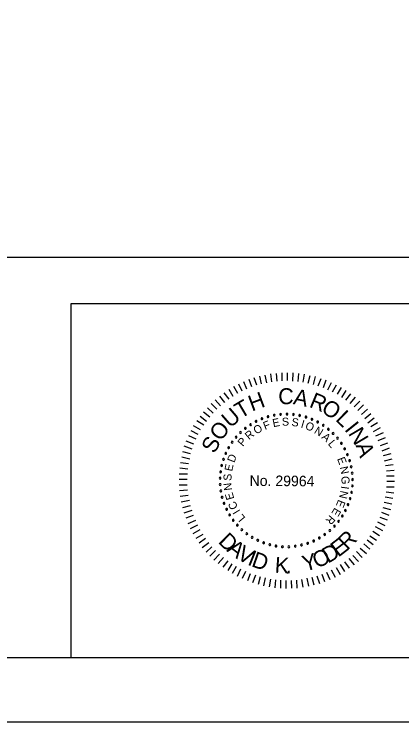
# Model space of a CAD drawing. Extents: x -133.1 to -97, y -1.7 to 20.3.
# Drawn here: x -110.95 to -107.94, y -1.69 to 3.81 of the extents above; entities that cross this region are included whole.
import ezdxf

# ---------------------------------------------------------------- set-up
doc = ezdxf.new("R2010")
doc.units = 0
for name, color, linetype in [('BR_AUTO DIMENSION', 7, 'Continuous'), ('BR_BORDER LINES', 7, 'Continuous'), ('BR_TEXT', 7, 'Continuous'), ('Level 31', 7, 'Continuous')]:
    doc.layers.add(name, color=color, linetype=linetype)

msp = doc.modelspace()

# ---------------------------------------------------------------- linework, layer by layer
at = {"layer": 'BR_AUTO DIMENSION'}
msp.add_lwpolyline([(-124.7207, 1.9196), (-106.7207, 1.9196), (-106.7207, 13.8928), (-124.7207, 13.8928)], close=True, dxfattribs=at)
at = {"layer": 'BR_BORDER LINES'}
for p, q in [((-110.5071, 1.5591), (-105.1419, 1.5591)), ((-110.5071, -1.191), (-110.5071, 1.5591)), ((-131.3076, -1.191), (-97.6416, -1.191))]:
    msp.add_line(p, q, dxfattribs=at)
at = {"layer": 'BR_TEXT'}
for p, q in [((-109.0262, 0.9348), (-109.0394, 0.9958)), ((-108.9849, 0.9447), (-108.999, 1.0041)), ((-108.9454, 0.9521), (-108.9543, 1.0131)), ((-108.9059, 0.9561), (-108.9097, 1.017)), ((-108.8664, 0.9584), (-108.8658, 1.0227)), ((-108.8243, 0.9606), (-108.8238, 1.0224)), ((-108.7823, 0.9577), (-108.78, 1.022)), ((-108.742, 0.9548), (-108.7372, 1.0156)), ((-108.7034, 0.9501), (-108.6926, 1.011)), ((-108.6631, 0.9421), (-108.6489, 1.0012)), ((-108.622, 0.9314), (-108.606, 0.9922)), ((-109.1406, 0.8954), (-109.1642, 0.9514)), ((-109.1019, 0.9122), (-109.1229, 0.9708)), ((-109.0623, 0.9248), (-109.0842, 0.9824)), ((-108.5852, 0.9208), (-108.5633, 0.9781)), ((-108.5458, 0.9076), (-108.5239, 0.9658)), ((-108.5099, 0.8902), (-108.482, 0.9457)), ((-109.2475, 0.8371), (-109.278, 0.8914)), ((-109.2122, 0.8608), (-109.2426, 0.9151)), ((-109.1777, 0.8785), (-109.2039, 0.9345)), ((-108.474, 0.8727), (-108.4427, 0.9282)), ((-108.4364, 0.8544), (-108.4042, 0.9082)), ((-108.4031, 0.8301), (-108.3692, 0.8839)), ((-109.3123, 0.7904), (-109.3522, 0.8405)), ((-109.2786, 0.8159), (-109.3177, 0.8668)), ((-108.3699, 0.8083), (-108.3334, 0.8587)), ((-108.3375, 0.7824), (-108.2968, 0.8318)), ((-109.3745, 0.7386), (-109.4188, 0.7827)), ((-109.3451, 0.7658), (-109.3868, 0.8107)), ((-108.3059, 0.7572), (-108.2627, 0.8014)), ((-108.2779, 0.7295), (-108.2346, 0.7729)), ((-109.4291, 0.6763), (-109.4786, 0.7154)), ((-109.4039, 0.7079), (-109.4474, 0.7503)), ((-108.2498, 0.6984), (-108.2022, 0.74)), ((-109.4551, 0.6431), (-109.5046, 0.683)), ((-108.2226, 0.6664), (-108.1759, 0.7046)), ((-108.1988, 0.6327), (-108.1496, 0.6718)), ((-109.5012, 0.5774), (-109.5549, 0.6096)), ((-109.4768, 0.6141), (-109.5306, 0.6472)), ((-108.1768, 0.6034), (-108.1242, 0.6355)), ((-109.5186, 0.5432), (-109.575, 0.5711)), ((-108.1548, 0.5663), (-108.1013, 0.5976)), ((-108.137, 0.5318), (-108.0793, 0.5588)), ((-109.5361, 0.5065), (-109.5933, 0.5318)), ((-108.1193, 0.4948), (-108.0624, 0.5192)), ((-109.5659, 0.4278), (-109.6275, 0.4506)), ((-109.5536, 0.468), (-109.6117, 0.4899)), ((-108.1025, 0.456), (-108.0456, 0.477)), ((-109.5782, 0.3918), (-109.639, 0.4069)), ((-108.0891, 0.4156), (-108.0314, 0.4374)), ((-108.079, 0.3794), (-108.0189, 0.3935)), ((-109.5854, 0.3498), (-109.6479, 0.3658)), ((-108.0708, 0.3373), (-108.0106, 0.3522)), ((-109.6006, 0.2727), (-109.6624, 0.2801)), ((-109.596, 0.3138), (-109.6569, 0.3221)), ((-108.0625, 0.3012), (-108.0033, 0.3084)), ((-109.6035, 0.2333), (-109.6679, 0.2338)), ((-108.056, 0.26), (-107.995, 0.2663)), ((-108.0546, 0.2205), (-107.9945, 0.22)), ((-109.6056, 0.1921), (-109.6682, 0.1926)), ((-108.0524, 0.1793), (-107.9915, 0.1788)), ((-109.6042, 0.1492), (-109.6686, 0.148)), ((-109.602, 0.1105), (-109.6638, 0.1033)), ((-108.0553, 0.1364), (-107.9952, 0.1342)), ((-109.598, 0.0693), (-109.659, 0.0604)), ((-108.0645, 0.0566), (-108.0054, 0.0467)), ((-108.0574, 0.0978), (-107.9965, 0.0896)), ((-109.5881, 0.0297), (-109.6508, 0.0165)), ((-108.0735, 0.0172), (-108.0135, 0.003)), ((-109.5815, -0.0124), (-109.6426, -0.0265)), ((-109.5698, -0.0493), (-109.6318, -0.0703)), ((-108.0824, -0.0248), (-108.0224, -0.0398)), ((-109.5582, -0.0881), (-109.6167, -0.1091)), ((-108.107, -0.1001), (-108.0506, -0.122)), ((-108.093, -0.0615), (-108.0357, -0.0835)), ((-109.5413, -0.1251), (-109.599, -0.1521)), ((-109.5244, -0.1613), (-109.5813, -0.1909)), ((-108.1245, -0.1368), (-108.0681, -0.1647)), ((-109.5076, -0.1984), (-109.5619, -0.2297)), ((-108.1612, -0.2095), (-108.1082, -0.2417)), ((-108.1428, -0.1727), (-108.0856, -0.2032)), ((-109.4838, -0.2355), (-109.5382, -0.2668)), ((-109.4626, -0.2648), (-109.5127, -0.3013)), ((-108.1838, -0.2462), (-108.1317, -0.2784)), ((-109.4372, -0.2985), (-109.4873, -0.3376)), ((-108.2306, -0.3084), (-108.1846, -0.3483)), ((-108.2063, -0.2752), (-108.1577, -0.3125)), ((-109.4125, -0.3321), (-109.4567, -0.373)), ((-109.3836, -0.3582), (-109.4286, -0.4032)), ((-108.2869, -0.3672), (-108.2444, -0.413)), ((-108.2583, -0.3417), (-108.2115, -0.3833)), ((-109.3547, -0.3884), (-109.3971, -0.4344)), ((-109.3222, -0.4144), (-109.363, -0.4613)), ((-108.3474, -0.4225), (-108.3075, -0.47)), ((-108.3155, -0.397), (-108.273, -0.4437)), ((-109.289, -0.4404), (-109.3289, -0.4882)), ((-109.2583, -0.4622), (-109.2896, -0.5142)), ((-109.2233, -0.4847), (-109.2546, -0.5386)), ((-108.4475, -0.4911), (-108.4162, -0.5455)), ((-108.4139, -0.4691), (-108.3808, -0.5217)), ((-108.3802, -0.448), (-108.3446, -0.4963)), ((-109.1891, -0.5048), (-109.2162, -0.5603)), ((-109.1523, -0.5222), (-109.1769, -0.5778)), ((-109.1139, -0.5397), (-109.1358, -0.5962)), ((-108.5578, -0.5443), (-108.5368, -0.6011)), ((-108.5216, -0.5274), (-108.4947, -0.5835)), ((-108.4855, -0.5106), (-108.455, -0.5666)), ((-109.0745, -0.552), (-109.0973, -0.6102)), ((-109.0386, -0.5644), (-109.0528, -0.6235)), ((-108.9974, -0.5716), (-109.0126, -0.6333)), ((-108.9581, -0.5831), (-108.968, -0.6413)), ((-108.9186, -0.5877), (-108.9234, -0.6494)), ((-108.8792, -0.5906), (-108.8797, -0.6524)), ((-108.8372, -0.5935), (-108.8377, -0.6544)), ((-108.7951, -0.5913), (-108.7939, -0.6531)), ((-108.7547, -0.589), (-108.7509, -0.6509)), ((-108.7161, -0.5851), (-108.7062, -0.6435)), ((-108.6756, -0.5742), (-108.6624, -0.6361)), ((-108.6344, -0.5677), (-108.6194, -0.627)), ((-108.5974, -0.556), (-108.5764, -0.6145))]:
    msp.add_line(p, q, dxfattribs=at)
for centre, start, end in [((-109.0235, 0.6646), 21.6807, 201.6807), ((-109.0235, 0.6646), 201.6807, 21.6807), ((-108.9763, 0.6806), 16.1422, 196.1422), ((-108.9763, 0.6806), 196.1422, 16.1422), ((-108.9278, 0.692), 10.6038, 190.6038), ((-108.9278, 0.692), 190.6038, 10.6038), ((-108.8784, 0.6987), 5.0653, 185.0653), ((-108.8784, 0.6987), 185.0653, 5.0653), ((-108.8286, 0.7006), 359.5268, 179.5268), ((-108.8286, 0.7006), 179.5268, 359.5268), ((-108.7789, 0.6977), 173.9884, 353.9884), ((-108.7789, 0.6977), 353.9884, 173.9884), ((-108.7296, 0.69), 168.4499, 348.4499), ((-108.7296, 0.69), 348.4499, 168.4499), ((-108.6814, 0.6776), 162.9114, 342.9114), ((-108.6814, 0.6776), 342.9114, 162.9114), ((-108.6345, 0.6606), 157.373, 337.373), ((-108.6345, 0.6606), 337.373, 157.373), ((-109.1121, 0.6192), 32.7576, 212.7576), ((-109.1121, 0.6192), 212.7576, 32.7576), ((-109.0689, 0.644), 27.2191, 207.2191), ((-109.0689, 0.644), 207.2191, 27.2191), ((-108.5896, 0.6391), 151.8345, 331.8345), ((-108.5896, 0.6391), 331.8345, 151.8345), ((-108.5469, 0.6134), 146.2961, 326.2961), ((-108.5469, 0.6134), 326.2961, 146.2961), ((-109.1903, 0.5577), 43.8345, 223.8345), ((-109.1903, 0.5577), 223.8345, 43.8345), ((-109.1527, 0.5903), 38.2961, 218.2961), ((-109.1527, 0.5903), 218.2961, 38.2961), ((-108.5069, 0.5837), 140.7576, 320.7576), ((-108.5069, 0.5837), 320.7576, 140.7576), ((-108.4699, 0.5503), 135.2191, 315.2191), ((-108.4699, 0.5503), 315.2191, 135.2191), ((-109.2246, 0.5215), 49.373, 229.373), ((-109.2246, 0.5215), 229.373, 49.373), ((-108.4363, 0.5134), 129.6807, 309.6807), ((-108.4363, 0.5134), 309.6807, 129.6807), ((-109.282, 0.4402), 60.4499, 240.4499), ((-109.282, 0.4402), 240.4499, 60.4499), ((-109.2553, 0.4822), 54.9114, 234.9114), ((-109.2553, 0.4822), 234.9114, 54.9114), ((-108.4065, 0.4735), 124.1422, 304.1422), ((-108.4065, 0.4735), 304.1422, 124.1422), ((-109.3045, 0.3957), 65.9884, 245.9884), ((-109.3045, 0.3957), 245.9884, 65.9884), ((-108.3806, 0.4309), 118.6038, 298.6038), ((-108.3806, 0.4309), 298.6038, 118.6038), ((-108.359, 0.3861), 113.0653, 293.0653), ((-108.359, 0.3861), 293.0653, 113.0653), ((-109.3227, 0.3493), 71.5268, 251.5268), ((-109.3227, 0.3493), 251.5268, 71.5268), ((-108.3418, 0.3393), 107.5268, 287.5268), ((-108.3418, 0.3393), 287.5268, 107.5268), ((-109.3363, 0.3014), 77.0653, 257.0653), ((-109.3363, 0.3014), 257.0653, 77.0653), ((-108.3292, 0.2911), 101.9884, 281.9884), ((-108.3292, 0.2911), 281.9884, 101.9884), ((-109.3452, 0.2524), 82.6038, 262.6038), ((-109.3452, 0.2524), 262.6038, 82.6038), ((-108.3213, 0.2419), 96.4499, 276.4499), ((-108.3213, 0.2419), 276.4499, 96.4499), ((-109.3493, 0.2027), 88.1422, 268.1422), ((-109.3493, 0.2027), 268.1422, 88.1422), ((-108.3182, 0.1921), 90.9114, 270.9114), ((-108.3182, 0.1921), 270.9114, 90.9114), ((-109.3486, 0.1529), 93.6807, 273.6807), ((-109.3431, 0.1033), 99.2191, 279.2191), ((-109.3486, 0.1529), 273.6807, 93.6807), ((-109.3431, 0.1033), 279.2191, 99.2191), ((-108.3199, 0.1423), 85.373, 265.373), ((-108.3199, 0.1423), 265.373, 85.373), ((-109.3328, 0.0546), 104.7576, 284.7576), ((-109.3328, 0.0546), 284.7576, 104.7576), ((-108.3265, 0.0929), 79.8345, 259.8345), ((-108.3265, 0.0929), 259.8345, 79.8345), ((-109.3179, 0.007), 110.2961, 290.2961), ((-109.3179, 0.007), 290.2961, 110.2961), ((-108.3536, -0.0028), 68.7576, 248.7576), ((-108.3536, -0.0028), 248.7576, 68.7576), ((-108.3377, 0.0444), 74.2961, 254.2961), ((-108.3377, 0.0444), 254.2961, 74.2961), ((-109.2985, -0.0389), 115.8345, 295.8345), ((-109.2985, -0.0389), 295.8345, 115.8345), ((-108.374, -0.0483), 63.2191, 243.2191), ((-108.374, -0.0483), 243.2191, 63.2191), ((-109.2747, -0.0826), 121.373, 301.373), ((-109.2747, -0.0826), 301.373, 121.373), ((-108.3986, -0.0916), 57.6807, 237.6807), ((-108.3986, -0.0916), 237.6807, 57.6807), ((-109.2468, -0.1239), 126.9114, 306.9114), ((-109.2468, -0.1239), 306.9114, 126.9114), ((-109.2151, -0.1624), 132.4499, 312.4499), ((-109.2151, -0.1624), 312.4499, 132.4499), ((-108.4599, -0.1701), 46.6038, 226.6038), ((-108.4273, -0.1323), 52.1422, 232.1422), ((-108.4273, -0.1323), 232.1422, 52.1422), ((-109.1798, -0.1975), 137.9884, 317.9884), ((-109.1798, -0.1975), 317.9884, 137.9884), ((-108.4959, -0.2045), 41.0653, 221.0653), ((-108.4959, -0.2045), 221.0653, 41.0653), ((-108.4599, -0.1701), 226.6038, 46.6038), ((-109.1413, -0.2291), 143.5268, 323.5268), ((-109.1413, -0.2291), 323.5268, 143.5268), ((-109.0999, -0.2569), 149.0653, 329.0653), ((-109.0999, -0.2569), 329.0653, 149.0653), ((-109.056, -0.2805), 334.6038, 154.6038), ((-108.577, -0.2622), 29.9884, 209.9884), ((-108.577, -0.2622), 209.9884, 29.9884), ((-108.5351, -0.2353), 35.5268, 215.5268), ((-108.5351, -0.2353), 215.5268, 35.5268), ((-109.056, -0.2805), 154.6038, 334.6038), ((-109.01, -0.2997), 160.1422, 340.1422), ((-109.01, -0.2997), 340.1422, 160.1422), ((-108.9624, -0.3145), 165.6807, 345.6807), ((-108.9624, -0.3145), 345.6807, 165.6807), ((-108.9136, -0.3245), 171.2191, 351.2191), ((-108.9136, -0.3245), 351.2191, 171.2191), ((-108.8641, -0.3299), 356.7576, 176.7576), ((-108.8641, -0.3299), 176.7576, 356.7576), ((-108.8142, -0.3304), 2.2961, 182.2961), ((-108.7646, -0.3261), 7.8345, 187.8345), ((-108.7646, -0.3261), 187.8345, 7.8345), ((-108.7156, -0.317), 13.373, 193.373), ((-108.7156, -0.317), 193.373, 13.373), ((-108.6677, -0.3032), 18.9114, 198.9114), ((-108.6677, -0.3032), 198.9114, 18.9114), ((-108.6214, -0.2849), 24.4499, 204.4499), ((-108.6214, -0.2849), 204.4499, 24.4499), ((-108.8142, -0.3304), 182.2961, 2.2961)]:
    msp.add_arc(centre, 0.00701, start, end, dxfattribs=at)
at = {"layer": 'Level 31'}
msp.add_lwpolyline([(-133.1409, -1.691), (-97.141, -1.691), (-97.141, 20.309), (-133.1409, 20.309)], close=True, dxfattribs=at)

# ---------------------------------------------------------------- texts
at = {"layer": 'BR_TEXT'}
for s, height, rotation, p in [('C', 0.1241, 359.5482, (-108.8971, 0.7782)), ('A', 0.1241, 348.1981, (-108.7857, 0.779)), ('H', 0.1241, 20.3637, (-109.1015, 0.7199)), ('R', 0.1241, 337.4344, (-108.6624, 0.7591)), ('T', 0.1241, 30.4992, (-109.1894, 0.6624)), ('O', 0.1239, 326.5869, (-108.5702, 0.7224)), ('U', 0.1241, 40.8022, (-109.2706, 0.5876)), ('L', 0.1241, 315.9488, (-108.4576, 0.6546)), ('E', 0.0622, 11.4103, (-108.9351, 0.5987)), ('S', 0.0622, 2.208, (-108.8672, 0.6097)), ('S', 0.0622, 352.6608, (-108.796, 0.6095)), ('O', 0.1241, 52.0267, (-109.3451, 0.4837)), ('O', 0.0622, 30.8477, (-109.0676, 0.541)), ('F', 0.0622, 20.6127, (-109.0002, 0.577)), ('I', 0.0622, 343.1136, (-108.7257, 0.5975)), ('O', 0.0622, 338.4392, (-108.6923, 0.5873)), ('N', 0.0622, 328.2042, (-108.6227, 0.5559)), ('I', 0.1241, 308.6613, (-108.3862, 0.5803)), ('R', 0.0622, 40.3949, (-109.1237, 0.4971)), ('N', 0.1241, 300.7037, (-108.3556, 0.5509)), ('S', 0.1239, 63.2511, (-109.3905, 0.3881)), ('P', 0.0622, 49.9421, (-109.1718, 0.4445)), ('A', 0.0622, 318.657, (-108.5637, 0.5159)), ('L', 0.0622, 309.4546, (-108.5139, 0.4686)), ('A', 0.1241, 289.4792, (-108.2964, 0.4579)), ('D', 0.0622, 69.0364, (-109.2388, 0.3192)), ('E', 0.0622, 291.049, (-108.44, 0.3533)), ('E', 0.0622, 78.2388, (-109.2553, 0.2526)), ('N', 0.0622, 281.8466, (-108.4179, 0.2882)), ('S', 0.0622, 87.786, (-109.2611, 0.1815)), ('No. 29964', 0.08175, 359.5268, (-109.1199, 0.1431)), ('G', 0.0622, 272.2995, (-108.4061, 0.2179)), ('N', 0.0622, 97.3332, (-109.2549, 0.1105)), ('I', 0.0622, 262.4084, (-108.4065, 0.1441)), ('E', 0.0622, 106.5355, (-109.2379, 0.044)), ('N', 0.0622, 257.7339, (-108.411, 0.1095)), ('C', 0.0622, 116.4266, (-109.208, -0.0235)), ('E', 0.0622, 248.1867, (-108.4291, 0.0406)), ('I', 0.0622, 121.1011, (-109.1899, -0.0534)), ('E', 0.0622, 238.9844, (-108.457, -0.0222)), ('L', 0.0622, 129.9595, (-109.1493, -0.1056)), ('R', 0.0622, 229.782, (-108.4947, -0.0797)), ('D', 0.1236, 315.4053, (-109.3698, -0.2962)), ('R', 0.1236, 44.5947, (-108.3589, -0.3617)), ('E', 0.1236, 37.5339, (-108.4295, -0.4156)), ('A', 0.1236, 322.8377, (-109.3032, -0.3618)), ('V', 0.1236, 330.5179, (-109.226, -0.42)), ('D', 0.1236, 30.1015, (-108.5104, -0.4626)), ('I', 0.1236, 338.1981, (-109.1418, -0.4674)), ('D', 0.1236, 340.7995, (-109.1119, -0.4808)), ('Y', 0.1236, 14.8649, (-108.6915, -0.5241)), ('O', 0.1236, 22.4212, (-108.5997, -0.4996)), ('K', 0.1236, 356.098, (-108.9267, -0.5314)), ('.', 0.1236, 3.1588, (-108.838, -0.5377))]:
    msp.add_text(s, height=height, rotation=rotation, dxfattribs=at).set_placement(p)

doc.saveas('drawing.dxf')
